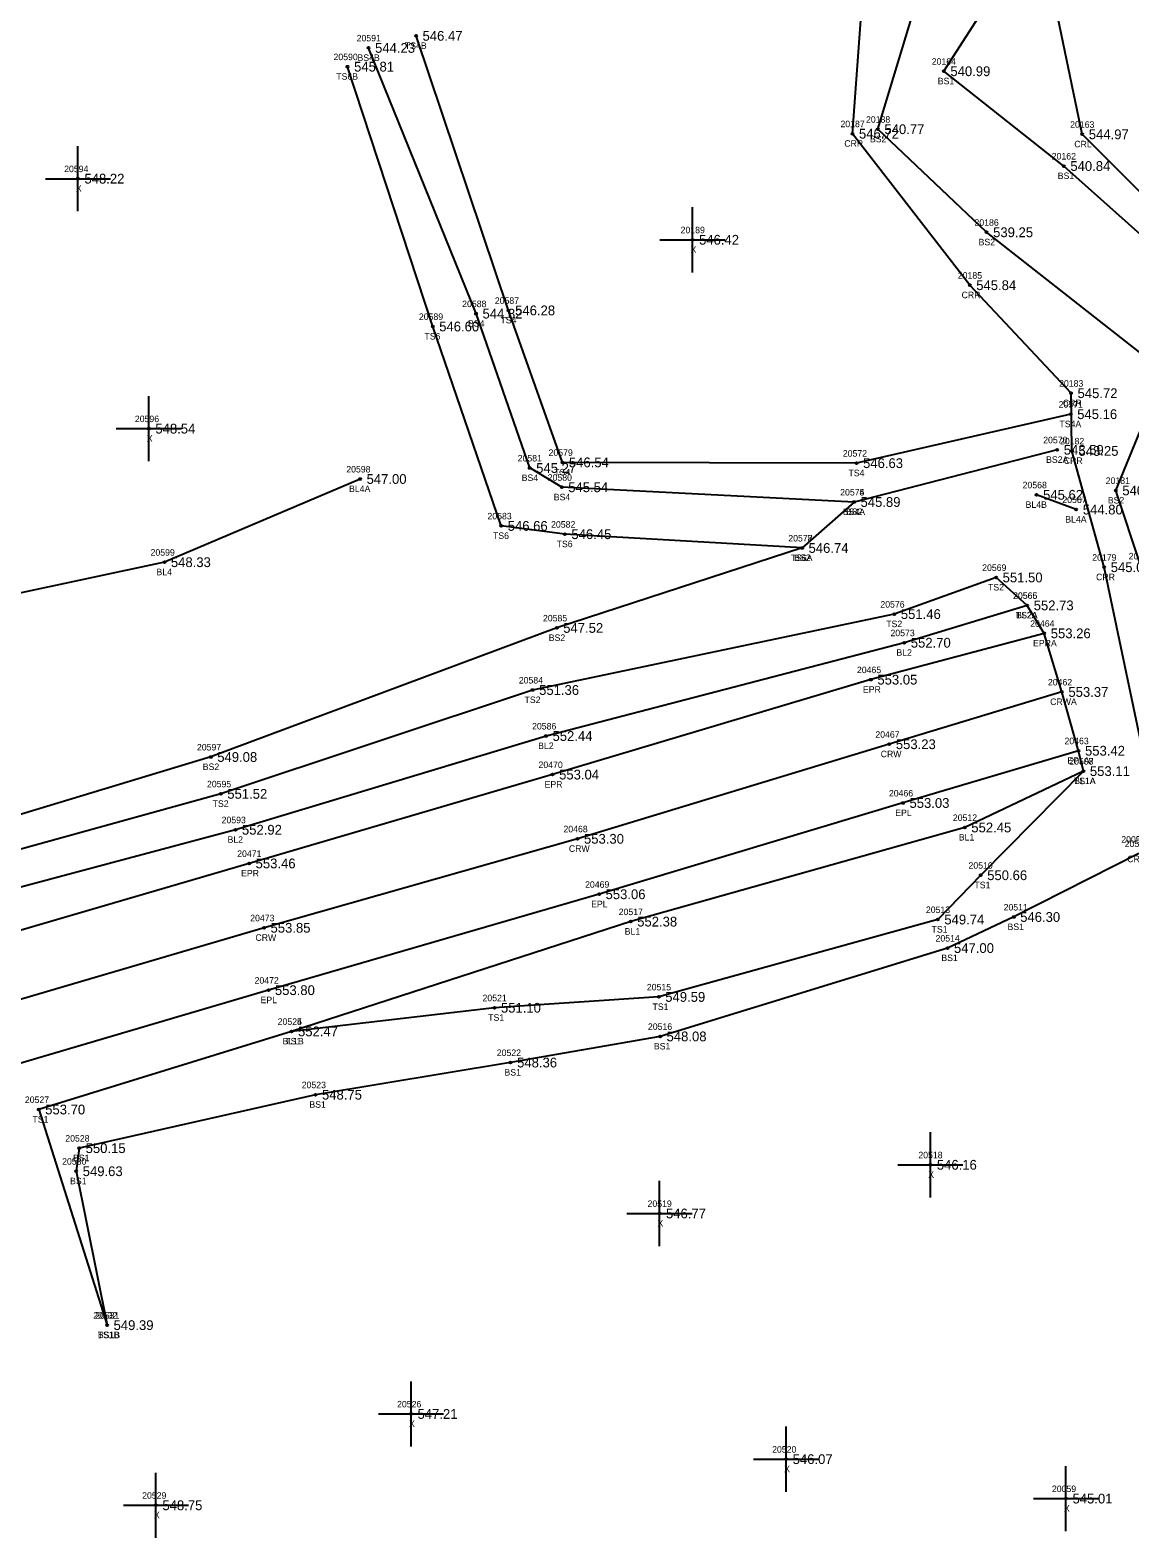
# Model space of a CAD drawing. Extents: x 1540443 to 1541844, y 887157 to 888162.
# Drawn here: x 1540968 to 1541136.9, y 887544 to 887775.4 of the extents above; entities that cross this region are included whole.
import ezdxf

# ---------------------------------------------------------------- set-up
doc = ezdxf.new("R2010")
doc.units = 0
for name, color, linetype in [('RD_DTM_BkLn1', 7, 'Continuous'), ('RD_DTM_BkLn2', 7, 'Continuous'), ('RD_DTM_BkLn_txCode', 7, 'Continuous'), ('RD_EX_H2O', 7, 'Continuous'), ('RD_EX_H2O_txCode', 7, 'Continuous'), ('RD_EX_Misc', 7, 'Continuous'), ('RD_EX_Misc_txCode', 7, 'Continuous'), ('RD_EX_Road', 7, 'Continuous'), ('RD_EX_Road_txCode', 7, 'Continuous'), ('RD_EX_TX_H2O_ELEV', 7, 'Continuous'), ('RD_EX_TX_Misc_ELEV', 7, 'Continuous'), ('RD_EX_TX_Road_ELEV', 7, 'Continuous'), ('RD_HC_Survey_ELEV', 7, 'Continuous'), ('RD_HC_Survey_txCode', 7, 'Continuous'), ('RD_SMD_Locator', 7, 'Continuous')]:
    doc.layers.add(name, color=color, linetype=linetype)

msp = doc.modelspace()

# ---------------------------------------------------------------- linework, layer by layer
at = {"layer": 'RD_DTM_BkLn1'}
msp.add_line((1541128.65, 887701.83), (1541122.55, 887704.09), dxfattribs=at)
for points in [[(1541018.68, 887706.52), (1540988.63, 887693.75), (1540942.45, 887683.87), (1540885.12, 887669.9), (1540845.12, 887653.21), (1540805.74, 887626.62)], [(1541121.11, 887687.12), (1541102.24, 887681.39), (1541047.23, 887667.07), (1540999.54, 887652.68), (1540951.37, 887639.83), (1540901.44, 887627.14), (1540855.78, 887612.94), (1540807.53, 887596.54), (1540760.49, 887584.4), (1540713.89, 887573.7)], [(1541126.44, 887673.83), (1541099.94, 887665.81), (1541052.06, 887651.29), (1541003.93, 887637.63), (1540955.85, 887623.48), (1540907.97, 887609.13), (1540859.88, 887595.48), (1540836.31, 887588.86), (1540811.54, 887582.34), (1540783.96, 887575.59), (1540763.17, 887570.39), (1540738.15, 887565.52), (1540714.18, 887561.19), (1540687.63, 887557.81), (1540664.59, 887555.61), (1540640.72, 887554.4), (1540614.88, 887554.02), (1540589.98, 887554.69), (1540565.01, 887555.56), (1540543.6, 887557.4), (1540515.55, 887560.7), (1540490.9, 887564.25), (1540466.38, 887568.75)], [(1541129.74, 887661.68), (1541111.53, 887653.03), (1541060.23, 887638.58), (1541008.15, 887621.73)]]:
    msp.add_lwpolyline(points, dxfattribs=at)
at = {"layer": 'RD_DTM_BkLn2'}
for points in [[(1541349.06, 887859.41), (1541301.9, 887838.51), (1541276.98, 887854.12), (1541250.17, 887847.68), (1541235.42, 887838.4), (1541226.46, 887818.66), (1541206.99, 887816.69), (1541177.91, 887783.05), (1541174.61, 887756.9), (1541155.39, 887744.58), (1541154.65, 887729.69), (1541126.74, 887754.56), (1541108.32, 887769.11), (1541148.46, 887831.42), (1541178.11, 887856.6), (1541159.66, 887905.22), (1541133.37, 887953.98), (1541101.85, 887998.23), (1541093.93, 888039.66), (1541072.92, 888058.86), (1541087, 888085), (1541104.04, 888122.31), (1541088.02, 888158.63)], [(1541146.1, 887665.49), (1541138.57, 887693.18), (1541134.72, 887704.76), (1541142.18, 887722.96), (1541114.88, 887744.39), (1541098.19, 887760.21), (1541108.65, 887794.85), (1541126.24, 887822.69), (1541166.01, 887866.51), (1541149.08, 887912.73), (1541115.84, 887949.01), (1541089.41, 887986.26), (1541082.08, 888036.68), (1541064.88, 888057.53), (1541079.32, 888092.84), (1541092.39, 888127.26), (1541076.18, 888157.56)], [(1541127.79, 887716.47), (1541094.91, 887708.95), (1541049.74, 887709.07), (1541041.49, 887732.4), (1541027.27, 887774.54)], [(1541094.52, 887702.99), (1541049.64, 887705.25), (1541044.72, 887708.21), (1541036.48, 887731.9), (1541019.98, 887772.69)], [(1541086.54, 887695.93), (1541050.13, 887698.05), (1541040.35, 887699.32), (1541029.83, 887729.93), (1541016.76, 887769.81)], [(1541125.73, 887711), (1541094.52, 887702.99), (1541086.54, 887695.93), (1541048.87, 887683.66), (1540995.75, 887663.85), (1540948.75, 887649.66), (1540899.3, 887637.78), (1540852.09, 887622.25), (1540804.6, 887608.33), (1540757.89, 887594.74), (1540710.97, 887581.88), (1540663.03, 887573.83), (1540613.52, 887571.27), (1540565.55, 887571.13), (1540516.75, 887576.29), (1540467.77, 887583.94)], [(1541121.11, 887687.12), (1541116.34, 887691.41), (1541100.71, 887685.78), (1541045.17, 887674.13), (1540997.29, 887658.19), (1540949.92, 887645.1), (1540900.33, 887634.17), (1540852.81, 887620.54), (1540805.55, 887604.61), (1540758.2, 887592.6), (1540711.88, 887580.02), (1540663.85, 887571.28), (1540613.62, 887569.93), (1540565.66, 887569.42), (1540516.87, 887574.64), (1540467.8, 887581.76)], [(1541129.74, 887661.68), (1541128.99, 887664.81), (1541126.44, 887673.83), (1541123.73, 887682.83), (1541121.11, 887687.12)], [(1541129.74, 887661.68), (1541113.97, 887645.7), (1541107.39, 887638.9), (1541064.54, 887627.02), (1541039.31, 887625.36), (1541008.15, 887621.73), (1540969.33, 887609.74), (1540979.83, 887576.64)], [(1541138.25, 887649.04), (1541119.04, 887639.29), (1541108.87, 887634.52), (1541064.74, 887620.96), (1541041.79, 887616.95), (1541011.83, 887612.01), (1540975.54, 887603.81), (1540975.09, 887600.27), (1540979.83, 887576.64)]]:
    msp.add_lwpolyline(points, dxfattribs=at)
at = {"layer": 'RD_EX_H2O'}
for points in [[(1541345.47, 887860.33), (1541299.81, 887843.04), (1541278.31, 887858.39), (1541248.14, 887850.88), (1541232.97, 887840.42), (1541206.44, 887819.7), (1541175.27, 887783.56), (1541168.89, 887762.72), (1541151.82, 887746.65), (1541151.42, 887737.55), (1541129.57, 887759.43), (1541125.03, 887781.17), (1541150.06, 887828.48), (1541182.67, 887854.92), (1541164.01, 887910.29), (1541139.24, 887954.07), (1541111.52, 888003.47), (1541100.67, 888047.04), (1541091.5, 888080.23), (1541107.64, 888120.67), (1541095.14, 888160.09)], [(1541139.32, 887662.55), (1541132.94, 887692.98), (1541127.99, 887710.83), (1541127.84, 887719.69), (1541112.29, 887736.27), (1541094.28, 887759.52), (1541097.04, 887797.31), (1541106.04, 887811.91), (1541109.47, 887816.01), (1541121.03, 887830.67), (1541155.26, 887878.19), (1541140.59, 887910.22), (1541112.01, 887944.26), (1541086.28, 887983.65), (1541077.88, 888035.59), (1541062.25, 888056.78), (1541074.93, 888096.19), (1541086.66, 888128.26), (1541074.68, 888157.66)]]:
    msp.add_lwpolyline(points, dxfattribs=at)
at = {"layer": 'RD_EX_Misc'}
for p, q in [((1540975.36, 887747.62), (1540975.36, 887757.62)), ((1540970.36, 887752.62), (1540980.36, 887752.62)), ((1541069.73, 887738.24), (1541069.73, 887748.24)), ((1541064.73, 887743.24), (1541074.73, 887743.24)), ((1540986.25, 887709.25), (1540986.25, 887719.25)), ((1540981.25, 887714.25), (1540991.25, 887714.25)), ((1541106.24, 887596.25), (1541106.24, 887606.25)), ((1541101.24, 887601.25), (1541111.24, 887601.25)), ((1541064.65, 887588.78), (1541064.65, 887598.78)), ((1541059.65, 887593.78), (1541069.65, 887593.78)), ((1541026.5, 887558.01), (1541026.5, 887568.01)), ((1541021.5, 887563.01), (1541031.5, 887563.01)), ((1541084.1, 887551.07), (1541084.1, 887561.07)), ((1541079.1, 887556.07), (1541089.1, 887556.07)), ((1541127.07, 887545.02), (1541127.07, 887555.02)), ((1540987.33, 887543.99), (1540987.33, 887553.99)), ((1541122.07, 887550.02), (1541132.07, 887550.02)), ((1540982.33, 887548.99), (1540992.33, 887548.99))]:
    msp.add_line(p, q, dxfattribs=at)
at = {"layer": 'RD_EX_Road'}
for points in [[(1541123.73, 887682.83), (1541097.11, 887675.72), (1541048.24, 887661.15), (1541001.64, 887647.51), (1540952.42, 887633.12), (1540904.06, 887618.5), (1540857.24, 887604.78), (1540833.63, 887598.38), (1540808.59, 887591.31), (1540783.7, 887584.16), (1540761.05, 887578.97), (1540736.42, 887574.18), (1540712.73, 887570.56), (1540686.82, 887567.49), (1540663.33, 887565.48), (1540639.94, 887564.35), (1540615, 887563.38), (1540590.61, 887563.9), (1540565.81, 887565.05), (1540541.4, 887567.22), (1540516.92, 887569.69), (1540492.5, 887573.72), (1540467.49, 887577.97)], [(1541128.99, 887664.81), (1541102.04, 887656.79), (1541055.37, 887642.78), (1541004.6, 887628.06), (1540958.93, 887614.62), (1540910.77, 887599.96), (1540863.12, 887586.35), (1540837, 887578.35), (1540814.37, 887572.63), (1540785.6, 887565.57), (1540765.56, 887561), (1540743.15, 887555.32), (1540714.84, 887552.19), (1540688.66, 887548.15), (1540665.15, 887545.04), (1540640.91, 887544.2), (1540614.99, 887544.1), (1540590.77, 887544.52), (1540565.35, 887545.64), (1540542.9, 887547.56), (1540513.68, 887550.75), (1540490.5, 887554.02), (1540464.65, 887559.04)]]:
    msp.add_lwpolyline(points, dxfattribs=at)
at = {"layer": 'RD_SMD_Locator'}
for centre in [(1541027.27, 887774.54), (1541019.98, 887772.69), (1541016.76, 887769.81), (1541108.32, 887769.11), (1541098.19, 887760.21), (1541094.28, 887759.52), (1541129.57, 887759.43), (1541126.74, 887754.56), (1540975.36, 887752.62), (1541114.88, 887744.39), (1541069.73, 887743.24), (1541112.29, 887736.27), (1541041.49, 887732.4), (1541029.83, 887729.93), (1541036.48, 887731.9), (1541127.84, 887719.69), (1541127.79, 887716.47), (1540986.25, 887714.25), (1541125.73, 887711), (1541127.99, 887710.83), (1541044.72, 887708.21), (1541049.74, 887709.07), (1541094.91, 887708.95), (1541018.68, 887706.52), (1541049.64, 887705.25), (1541134.72, 887704.76), (1541094.52, 887702.99), (1541094.52, 887702.99), (1541122.55, 887704.09), (1541128.65, 887701.83), (1541040.35, 887699.32), (1541050.13, 887698.05), (1541086.54, 887695.93), (1541086.54, 887695.93), (1540988.63, 887693.75), (1541132.94, 887692.98), (1541116.34, 887691.41), (1541121.11, 887687.12), (1541121.11, 887687.12), (1541048.87, 887683.66), (1541100.71, 887685.78), (1541102.24, 887681.39), (1541123.73, 887682.83), (1541097.11, 887675.72), (1541045.17, 887674.13), (1541126.44, 887673.83), (1541047.23, 887667.07), (1541099.94, 887665.81), (1540995.75, 887663.85), (1541128.99, 887664.81), (1541048.24, 887661.15), (1541129.74, 887661.68), (1541129.74, 887661.68), (1540997.29, 887658.19), (1541102.04, 887656.79), (1540999.54, 887652.68), (1541052.06, 887651.29), (1541111.53, 887653.03), (1541001.64, 887647.51), (1541113.97, 887645.7), (1541055.37, 887642.78), (1541003.93, 887637.63), (1541060.23, 887638.58), (1541107.39, 887638.9), (1541119.04, 887639.29), (1541108.87, 887634.52), (1541004.6, 887628.06), (1541064.54, 887627.02), (1541039.31, 887625.36), (1541008.15, 887621.73), (1541008.15, 887621.73), (1541064.74, 887620.96), (1541041.79, 887616.95), (1541011.83, 887612.01), (1540969.33, 887609.74), (1540975.54, 887603.81), (1541106.24, 887601.25), (1540975.09, 887600.27), (1541064.65, 887593.78), (1540979.83, 887576.64), (1540979.83, 887576.64), (1541026.5, 887563.01), (1541084.1, 887556.07), (1541127.07, 887550.02), (1540987.33, 887548.99)]:
    msp.add_circle(centre, 0.15, dxfattribs=at)

# ---------------------------------------------------------------- texts
at = {"layer": 'RD_DTM_BkLn_txCode'}
for s, p in [('20591', (1541018.15, 887773.69)), ('20590', (1541014.6, 887770.81)), ('TS4B', (1541025.56, 887772.54)), ('BS4B', (1541018.28, 887770.69)), ('20164', (1541106.46, 887770.11)), ('TS6B', (1541015.02, 887767.81)), ('BS1', (1541107.38, 887767.11)), ('20188', (1541096.36, 887761.21)), ('BS2', (1541096.97, 887758.21)), ('20162', (1541124.88, 887755.56)), ('BS1', (1541125.8, 887752.56)), ('20186', (1541113.02, 887745.39)), ('BS2', (1541113.65, 887742.39)), ('20588', (1541034.36, 887732.9)), ('20587', (1541039.37, 887733.4)), ('20589', (1541027.71, 887730.93)), ('BS4', (1541035.25, 887729.9)), ('TS4', (1541040.24, 887730.4)), ('TS6', (1541028.56, 887727.93)), ('20571', (1541125.95, 887717.47)), ('TS4A', (1541126.06, 887714.47)), ('20570', (1541123.57, 887712)), ('20581', (1541042.88, 887709.21)), ('20579', (1541047.62, 887710.07)), ('20572', (1541092.8, 887709.95)), ('BS2A', (1541124.01, 887709)), ('20598', (1541016.56, 887707.52)), ('BS4', (1541043.49, 887706.21)), ('20580', (1541047.49, 887706.25)), ('TS4', (1541048.5, 887707.07)), ('TS4', (1541093.67, 887706.95)), ('BL4A', (1541016.99, 887704.52)), ('20574', (1541092.4, 887703.99)), ('20575', (1541092.4, 887703.99)), ('20568', (1541120.41, 887705.09)), ('20181', (1541133.17, 887705.76)), ('BS4', (1541048.42, 887703.25)), ('BL4B', (1541120.87, 887702.09)), ('20567', (1541126.51, 887702.83)), ('BS2', (1541133.49, 887702.76)), ('20583', (1541038.24, 887700.32)), ('20582', (1541048.01, 887699.05)), ('BS4A', (1541092.8, 887700.99)), ('BS2', (1541093.29, 887700.99)), ('BL4A', (1541126.96, 887699.83)), ('TS6', (1541039.09, 887697.32)), ('20577', (1541084.43, 887696.93)), ('20578', (1541084.43, 887696.93)), ('20599', (1540986.51, 887694.75)), ('TS6', (1541048.86, 887696.05)), ('TS6A', (1541084.79, 887693.93)), ('BS2', (1541085.32, 887693.93)), ('20569', (1541114.2, 887692.41)), ('20180', (1541136.7, 887694.18)), ('BL4', (1540987.42, 887691.75)), ('TS2', (1541115.09, 887689.41)), ('20566', (1541118.94, 887688.12)), ('20565', (1541118.96, 887688.12)), ('20576', (1541098.57, 887686.78)), ('TS2A', (1541119.37, 887685.12)), ('BL2A', (1541119.41, 887685.12)), ('20585', (1541046.76, 887684.66)), ('TS2', (1541099.47, 887683.78)), ('BS2', (1541047.65, 887681.66)), ('20573', (1541100.12, 887682.39)), ('BL2', (1541101.03, 887679.39)), ('20584', (1541043.05, 887675.13)), ('TS2', (1541043.93, 887672.13)), ('20586', (1541045.09, 887668.07)), ('20597', (1540993.63, 887664.85)), ('BL2', (1541046.02, 887665.07)), ('20507', (1541127.58, 887662.68)), ('20508', (1541127.58, 887662.68)), ('BS2', (1540994.52, 887661.85)), ('TS1A', (1541128.29, 887659.68)), ('BL1A', (1541128.33, 887659.68)), ('20595', (1540995.17, 887659.19)), ('TS2', (1540996.04, 887656.19)), ('20593', (1540997.42, 887653.68)), ('20512', (1541109.7, 887654.03)), ('BL2', (1540998.33, 887650.68)), ('BL1', (1541110.61, 887651.03)), ('20509', (1541136.09, 887650.04)), ('20510', (1541112.1, 887646.7)), ('TS1', (1541113.01, 887643.7)), ('20517', (1541058.39, 887639.58)), ('20513', (1541105.56, 887639.9)), ('20511', (1541117.49, 887640.29)), ('BL1', (1541059.31, 887636.58)), ('TS1', (1541106.43, 887636.9)), ('BS1', (1541118.09, 887637.29)), ('20514', (1541107.04, 887635.52)), ('BS1', (1541107.93, 887632.52)), ('20515', (1541062.71, 887628.02)), ('20521', (1541037.48, 887626.36)), ('TS1', (1541063.58, 887625.02)), ('20524', (1541006.03, 887622.73)), ('20525', (1541006.03, 887622.73)), ('TS1', (1541038.35, 887623.36)), ('20516', (1541062.88, 887621.96)), ('BL1B', (1541006.76, 887619.73)), ('TS1', (1541007.19, 887619.73)), ('BS1', (1541063.79, 887618.96)), ('20522', (1541039.67, 887617.95)), ('BS1', (1541040.85, 887614.95)), ('20523', (1541009.72, 887613.01)), ('20527', (1540967.21, 887610.74)), ('BS1', (1541010.89, 887610.01)), ('TS1', (1540968.37, 887607.74)), ('20528', (1540973.42, 887604.81)), ('BS1', (1540974.6, 887601.81)), ('20530', (1540972.93, 887601.27)), ('BS1', (1540974.15, 887598.27)), ('20532', (1540977.71, 887577.64)), ('20531', (1540977.99, 887577.64)), ('TS1B', (1540978.39, 887574.64)), ('BS1B', (1540978.41, 887574.64))]:
    msp.add_text(s, height=1, dxfattribs=at).set_placement(p)
at = {"layer": 'RD_EX_H2O_txCode'}
for s, p in [('20187', (1541092.44, 887760.52)), ('20163', (1541127.71, 887760.43)), ('CRR', (1541093.03, 887757.52)), ('CRL', (1541128.34, 887757.43)), ('20185', (1541110.46, 887737.27)), ('CRR', (1541111.04, 887734.27)), ('20183', (1541126.01, 887720.69)), ('CRR', (1541126.59, 887717.69)), ('20182', (1541126.15, 887711.83)), ('CRR', (1541126.73, 887708.83)), ('20179', (1541131.1, 887693.98)), ('CRR', (1541131.69, 887690.98)), ('20053', (1541135.56, 887650.7)), ('CRR', (1541136.47, 887647.7))]:
    msp.add_text(s, height=1, dxfattribs=at).set_placement(p)
at = {"layer": 'RD_EX_Misc_txCode'}
for s, p in [('20594', (1540973.24, 887753.62)), ('X', (1540975.04, 887750.62)), ('20189', (1541067.9, 887744.24)), ('X', (1541069.42, 887741.24)), ('20596', (1540984.1, 887715.25)), ('X', (1540985.93, 887712.25)), ('20518', (1541104.4, 887602.25)), ('X', (1541105.92, 887599.25)), ('20519', (1541062.82, 887594.78)), ('X', (1541064.34, 887591.78)), ('20526', (1541024.36, 887564.01)), ('X', (1541026.19, 887561.01)), ('20520', (1541081.95, 887557.07)), ('X', (1541083.79, 887554.07)), ('20059', (1541124.91, 887551.02)), ('20529', (1540985.22, 887549.99)), ('X', (1540987.02, 887546.99)), ('X', (1541126.75, 887548.02))]:
    msp.add_text(s, height=1, dxfattribs=at).set_placement(p)
at = {"layer": 'RD_EX_Road_txCode'}
for s, p in [('20464', (1541121.58, 887683.83)), ('EPRA', (1541122.01, 887680.83)), ('20465', (1541094.97, 887676.72)), ('EPR', (1541095.89, 887673.72)), ('20463', (1541126.84, 887665.81)), ('20470', (1541046.08, 887662.15)), ('EPLA', (1541127.29, 887662.81)), ('EPR', (1541047.01, 887659.15)), ('20466', (1541099.88, 887657.79)), ('EPL', (1541100.84, 887654.79)), ('20471', (1540999.81, 887648.51)), ('EPR', (1541000.41, 887645.51)), ('20469', (1541053.23, 887643.78)), ('EPL', (1541054.16, 887640.78)), ('20472', (1541002.48, 887629.06)), ('EPL', (1541003.39, 887626.06))]:
    msp.add_text(s, height=1, dxfattribs=at).set_placement(p)
at = {"layer": 'RD_EX_TX_H2O_ELEV'}
for s, p in [('546.72', (1541095.28, 887758.77)), ('544.97', (1541130.57, 887758.68)), ('545.84', (1541113.29, 887735.52)), ('545.72', (1541128.84, 887718.94)), ('543.25', (1541128.99, 887710.08)), ('545.04', (1541133.94, 887692.23))]:
    msp.add_text(s, height=1.5, dxfattribs=at).set_placement(p)
at = {"layer": 'RD_EX_TX_Misc_ELEV'}
for s, p in [('546.47', (1541028.27, 887773.79)), ('544.23', (1541020.98, 887771.94)), ('545.81', (1541017.76, 887769.06)), ('540.99', (1541109.32, 887768.36)), ('540.77', (1541099.19, 887759.46)), ('548.22', (1540976.36, 887751.87)), ('540.84', (1541127.74, 887753.81)), ('546.42', (1541070.73, 887742.49)), ('539.25', (1541115.88, 887743.64)), ('544.82', (1541037.48, 887731.15)), ('546.28', (1541042.49, 887731.65)), ('546.60', (1541030.83, 887729.18)), ('545.16', (1541128.79, 887715.72)), ('548.54', (1540987.25, 887713.5)), ('543.59', (1541126.73, 887710.25)), ('546.54', (1541050.74, 887708.32)), ('546.63', (1541095.91, 887708.2)), ('547.00', (1541019.68, 887705.77)), ('545.27', (1541045.72, 887707.46)), ('545.54', (1541050.64, 887704.5)), ('545.62', (1541123.55, 887703.34)), ('540.78', (1541135.72, 887704.01)), ('545.89', (1541095.52, 887702.24)), ('545.89', (1541095.52, 887702.24)), ('544.80', (1541129.65, 887701.08)), ('546.66', (1541041.35, 887698.57)), ('546.45', (1541051.13, 887697.3)), ('546.74', (1541087.54, 887695.18)), ('546.74', (1541087.54, 887695.18)), ('548.33', (1540989.63, 887693)), ('551.50', (1541117.34, 887690.66)), ('551.46', (1541101.71, 887685.03)), ('552.73', (1541122.11, 887686.37)), ('552.73', (1541122.11, 887686.37)), ('547.52', (1541049.87, 887682.91)), ('552.70', (1541103.24, 887680.64)), ('551.36', (1541046.17, 887673.38)), ('552.44', (1541048.23, 887666.32)), ('549.08', (1540996.75, 887663.1)), ('553.11', (1541130.74, 887660.93)), ('553.11', (1541130.74, 887660.93)), ('551.52', (1540998.29, 887657.44)), ('552.45', (1541112.53, 887652.28)), ('552.92', (1541000.54, 887651.93)), ('550.66', (1541114.97, 887644.95)), ('546.30', (1541120.04, 887638.54)), ('552.38', (1541061.23, 887637.83)), ('549.74', (1541108.39, 887638.15)), ('547.00', (1541109.87, 887633.77)), ('551.10', (1541040.31, 887624.61)), ('549.59', (1541065.54, 887626.27)), ('552.47', (1541009.15, 887620.98)), ('552.47', (1541009.15, 887620.98)), ('548.08', (1541065.74, 887620.21)), ('548.36', (1541042.79, 887616.2)), ('548.75', (1541012.83, 887611.26)), ('553.70', (1540970.33, 887608.99)), ('550.15', (1540976.54, 887603.06)), ('549.63', (1540976.09, 887599.52)), ('546.16', (1541107.24, 887600.5)), ('546.77', (1541065.65, 887593.03)), ('549.39', (1540980.83, 887575.89)), ('549.39', (1540980.83, 887575.89)), ('547.21', (1541027.5, 887562.26)), ('546.07', (1541085.1, 887555.32)), ('548.75', (1540988.33, 887548.24)), ('545.01', (1541128.07, 887549.27))]:
    msp.add_text(s, height=1.5, dxfattribs=at).set_placement(p)
at = {"layer": 'RD_EX_TX_Road_ELEV'}
for s, p in [('553.26', (1541124.73, 887682.08)), ('553.05', (1541098.11, 887674.97)), ('553.42', (1541129.99, 887664.06)), ('553.04', (1541049.24, 887660.4)), ('553.03', (1541103.04, 887656.04)), ('553.46', (1541002.64, 887646.76)), ('553.06', (1541056.37, 887642.03)), ('553.80', (1541005.6, 887627.31))]:
    msp.add_text(s, height=1.5, dxfattribs=at).set_placement(p)
at = {"layer": 'RD_HC_Survey_ELEV'}
for s, p in [('553.37', (1541127.44, 887673.08)), ('553.23', (1541100.94, 887665.06)), ('553.30', (1541053.06, 887650.54)), ('553.85', (1541004.93, 887636.88))]:
    msp.add_text(s, height=1.5, dxfattribs=at).set_placement(p)
at = {"layer": 'RD_HC_Survey_txCode'}
for s, p in [('20462', (1541124.3, 887674.83)), ('CRWA', (1541124.64, 887671.83)), ('20467', (1541097.8, 887666.81)), ('CRW', (1541098.62, 887663.81)), ('20468', (1541049.91, 887652.29)), ('CRW', (1541050.74, 887649.29)), ('20473', (1541001.81, 887638.63)), ('CRW', (1541002.61, 887635.63))]:
    msp.add_text(s, height=1, dxfattribs=at).set_placement(p)

doc.saveas('drawing.dxf')
